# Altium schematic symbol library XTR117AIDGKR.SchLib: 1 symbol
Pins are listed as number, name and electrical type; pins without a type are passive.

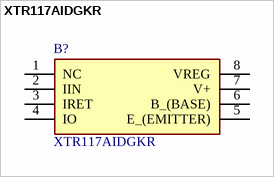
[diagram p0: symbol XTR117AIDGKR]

## XTR117AIDGKR
designator B?
Sensor Interface XTR117 4-20mA Crnt Loop Transmitter; Manufacturer_Name: Texas Instruments; Geometry.Height: 1.1mm
footprint SOP65P490X110-8N
pins: 1 NC, 2 IIN, 3 IRET, 4 IO, 5 E_(EMITTER), 6 B_(BASE), 7 V+, 8 VREG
